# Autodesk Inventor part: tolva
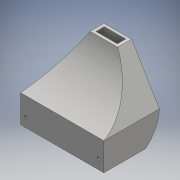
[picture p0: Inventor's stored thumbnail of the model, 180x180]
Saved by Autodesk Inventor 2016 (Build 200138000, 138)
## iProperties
Created: 2016-06
Part Number: tolva
Material: Generic
Document SubType Name: Modeling
Designer: yesi alvarez
Mass: 56.6751 g
Surface Area: 390.359 cm^2
Volume: 56.6751 cm^3
Density: 1 g/cm^3
Appearance: Default
Author: yesi alvarez
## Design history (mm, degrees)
sketch "Sketch2"
  geometry: L1 (0, 0)-(90, 0); L2 (90, 0)-(90, 60); L3 (90, 60)-(0, 60); L4 (0, 60)-(0, 0)
  constraints: 8 end point, 2 parallel, 1 horizontal, 1 perpendicular
  dimensions: "d11" = 90 distance of L3.end L2.end; "d12" = 60 distance of L2.end L1.end
workplane "Work Plane1"
sketch "Sketch3"
  geometry: L1 (30, 60)-(60, 60); L2 (60, 60)-(60, 45); L3 (60, 45)-(30, 45); L4 (30, 45)-(30, 60); 1 further point
  constraints: 8 end point, 2 parallel, 1 horizontal, 1 perpendicular
  dimensions: "d14" = 60 vertical distance of point (0, 0) L1.start; "d15" = 30 horizontal distance of L1.start point (0, 0); "d16" = 30 distance of L2.end L3.end; "d17" = 15 distance of L1.end L2.end
workplane "Work Plane2"
sketch "Sketch4"
  geometry: L1 (0, 0)-(90, 0); L2 (90, 0)-(90, 60); L3 (90, 60)-(0, 60); L4 (0, 60)-(0, 0)
  constraints: 8 end point, 2 parallel, 1 horizontal, 1 perpendicular
  dimensions: "d19" = 90 distance of L3.end L2.end; "d20" = 60 distance of L2.end L1.end
loft "Loft1" sketch "Sketch4" dims "d21" = 0, "d22" = 90 deg, "d23" = 0, "d24" = 90 deg
sketch "Sketch5"
  geometry: L1 (90, 0)-(90, 60) reference; L2 (0, 0)-(90, 0); L3 (90, 0)-(90, 60); L4 (90, 60)-(0, 60); L5 (0, 60)-(0, 0)
  constraints: 8 end point, 2 parallel, 1 horizontal, 1 perpendicular
  dimensions: "d25" = 90 distance of L4.end L1.end (derived); "d26" = 60 distance of L1.end L2.end (derived)
loft "Loft2" dims "d27" = 0, "d28" = 90 deg, "d29" = 0, "d30" = 90 deg
  node "Edges1"
workplane "Work Plane3"
sketch "Sketch6"
  geometry: L1 (67.082, 0)-(53.666, -26.833) reference; L2 (-22.361, -44.721)-(-8.944, -51.43) reference; L3 (53.666, -26.833)-(0, 0) reference; L4 (53.666, -26.833)-(-8.944, -51.43); A1 r 63.248 centre (41.946, -88.985) between (53.666, -26.833) and (-8.944, -51.43)
  constraints: 2 end point, 2 point on circle, 1 centre point
extrude "Extrusion2" cut sketch "Sketch6" distance "d31" = 100; taper "d32" = 0 deg
sketch "Sketch7"
  geometry: L1 (0, 60)-(0, 0) reference; L2 (30, 60)-(80, 60) reference; L3 (0, 45)-(0, 60); L4 (30, 60)-(30, 0) reference; L5 (30, 60)-(0, 60); A1 r 41.029 centre (31.746, 19.008) between (30, 60) and (0, 45)
  constraints: 4 end point, 2 point on circle, 1 centre point, 1 perpendicular, 1 point on line, 1 vertical
  dimensions: "d33" = 45 distance of L3.start L1.end
extrude "Extrusion3" cut sketch "Sketch7" distance "d34" = 100; taper "d35" = 0 deg
shell "Shell2" dims "d36" = 3
sketch "Sketch8"
  geometry: L1 (87, 0)-(87, 27.775) reference; L2 (3, 0)-(3, 27.775) reference; L3 (0, 0)-(90, 0) reference; C1 r 1.5 at (84.5, 10.53); C2 r 1.5 at (5.5, 10); 2 further points
  constraints: 2 centre point, 2 coincident
  dimensions: "d37" = 2.5 distance from line of L1 point (84.5, 10.53); "d38" = 2.5 distance from line of L2 point (5.5, 10); "d39" = 10 distance from line of point (5.5, 10) L3; "d40" = 3 diameter of C1; "d41" = 3 diameter of C2
extrude "Extrusion4" cut sketch "Sketch8" distance "d42" = 10; taper "d43" = 0 deg
thread "Thread1" dims "d44" = 10, "d45" = 0
thread "Thread2" dims "d46" = 10, "d47" = 0
body "Solid2"
